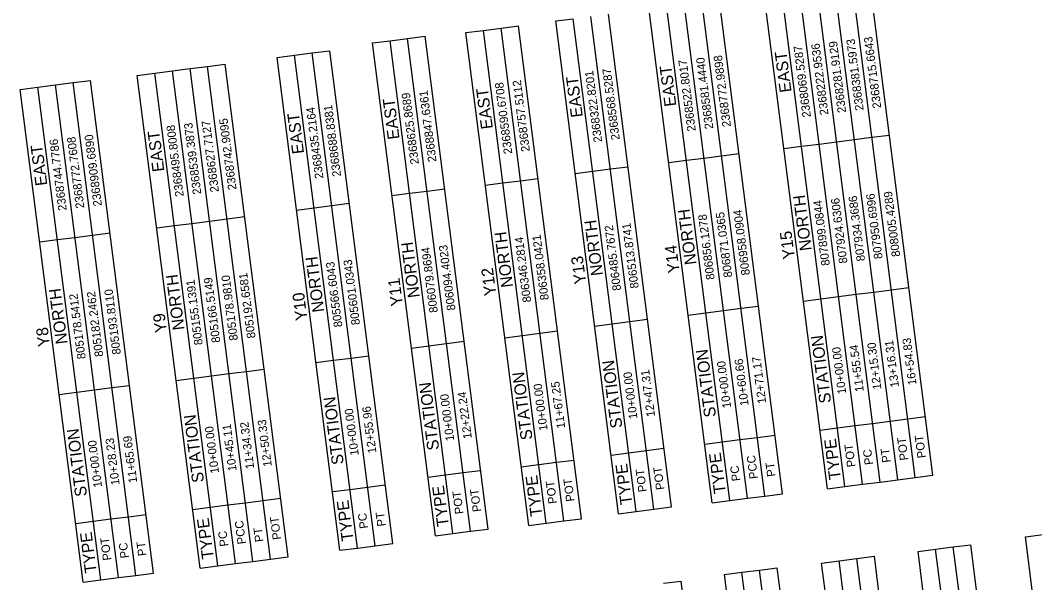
# Model space of a CAD drawing. Extents: x 2364621 to 2374814, y 792603 to 806745.
# Drawn here: x 2366776 to 2370831, y 796538 to 798784 of the extents above; entities that cross this region are included whole.
import ezdxf

# ---------------------------------------------------------------- set-up
doc = ezdxf.new("R2010")
doc.units = 0
for name, color, linetype in [('CTL Sheet Notes CELL', 7, 'Continuous'), ('CTL Sheet Table Cell', 7, 'Continuous'), ('CTL Sheet Text', 7, 'Continuous')]:
    doc.layers.add(name, color=color, linetype=linetype)

msp = doc.modelspace()

# ---------------------------------------------------------------- linework, layer by layer
at = {"layer": 'CTL Sheet Table Cell'}
for p, q in [((2370353.2, 796957.9), (2370101.8, 798926.4)), ((2370423.5, 796966.9), (2370172.1, 798935.4)), ((2370072, 796922), (2369820.6, 798890.5)), ((2370142.3, 796931), (2369890.9, 798899.5)), ((2370212.6, 796939.9), (2369961.2, 798908.5)), ((2370282.9, 796948.9), (2370031.5, 798917.4)), ((2369682, 796874.9), (2369430.6, 798843.4)), ((2369752.3, 796883.9), (2369500.9, 798852.4)), ((2369822.6, 796892.9), (2369571.2, 798861.4)), ((2370001.7, 796913), (2369750.3, 798881.5)), ((2369378.3, 796840.2), (2369126.9, 798808.7)), ((2369541.4, 796857), (2369290, 798825.5)), ((2369611.7, 796865.9), (2369360.3, 798834.4)), ((2368697.3, 798753), (2368767.6, 798761.9)), ((2369019, 796793.4), (2368767.6, 798761.9)), ((2368916, 798781.8), (2368986.3, 798790.8)), ((2369167.4, 796813.3), (2368916, 798781.8)), ((2369237.7, 796822.2), (2368986.3, 798790.8)), ((2369308, 796831.2), (2369056.6, 798799.7)), ((2368324.1, 798711.8), (2368394.4, 798720.8)), ((2368645.8, 796752.3), (2368394.4, 798720.8)), ((2368556.7, 798735), (2368627, 798744)), ((2368808.1, 796766.5), (2368556.7, 798735)), ((2368627, 798744), (2368697.3, 798753)), ((2368878.4, 796775.5), (2368627, 798744)), ((2368948.7, 796784.4), (2368697.3, 798753)), ((2368183.5, 798693.8), (2368253.8, 798702.8)), ((2368434.9, 796725.3), (2368183.5, 798693.8)), ((2368253.8, 798702.8), (2368324.1, 798711.8)), ((2368505.2, 796734.3), (2368253.8, 798702.8)), ((2368575.5, 796743.3), (2368324.1, 798711.8)), ((2367801.9, 798635.9), (2367872.2, 798644.8)), ((2367872.2, 798644.8), (2367942.5, 798653.8)), ((2368123.7, 796676.3), (2367872.2, 798644.8)), ((2367942.5, 798653.8), (2368012.8, 798662.8)), ((2368194, 796685.3), (2367942.5, 798653.8)), ((2368264.3, 796694.3), (2368012.8, 798662.8)), ((2367454.3, 798591.5), (2367524.6, 798600.5)), ((2367524.6, 798600.5), (2367594.9, 798609.4)), ((2367776, 796632), (2367524.6, 798600.5)), ((2367846.3, 796640.9), (2367594.9, 798609.4)), ((2368053.4, 796667.3), (2367801.9, 798635.9)), ((2367243.4, 798564.5), (2367313.7, 798573.5)), ((2367494.8, 796596), (2367243.4, 798564.5)), ((2367313.7, 798573.5), (2367384, 798582.5)), ((2367565.1, 796605), (2367313.7, 798573.5)), ((2367384, 798582.5), (2367454.3, 798591.5)), ((2367635.4, 796614), (2367384, 798582.5)), ((2367705.7, 796623), (2367454.3, 798591.5)), ((2366775.7, 798508.6), (2366846, 798517.6)), ((2366846, 798517.6), (2366916.3, 798526.6)), ((2367097.4, 796549.1), (2366846, 798517.6)), ((2366916.3, 798526.6), (2366986.6, 798535.6)), ((2367167.7, 796558.1), (2366916.3, 798526.6)), ((2366986.6, 798535.6), (2367056.9, 798544.5)), ((2367238, 796567), (2366986.6, 798535.6)), ((2367308.3, 796576), (2367056.9, 798544.5)), ((2367027.1, 796540.1), (2366775.7, 798508.6)), ((2370109.3, 798308.1), (2370179.6, 798317.1)), ((2370179.6, 798317.1), (2370249.9, 798326.1)), ((2369828.1, 798272.2), (2369898.4, 798281.2)), ((2369898.4, 798281.2), (2369968.7, 798290.2)), ((2369968.7, 798290.2), (2370039, 798299.2)), ((2370039, 798299.2), (2370109.3, 798308.1)), ((2369438.1, 798225.1), (2369508.4, 798234.1)), ((2369508.4, 798234.1), (2369578.7, 798243.1)), ((2369578.7, 798243.1), (2369649.1, 798252.1)), ((2369134.4, 798190.4), (2369204.7, 798199.4)), ((2369367.8, 798216.2), (2369438.1, 798225.1)), ((2368775.1, 798143.7), (2368845.4, 798152.6)), ((2368993.8, 798172.5), (2369064.1, 798181.5)), ((2369064.1, 798181.5), (2369134.4, 798190.4)), ((2368401.9, 798102.5), (2368472.2, 798111.5)), ((2368634.5, 798125.7), (2368704.8, 798134.7)), ((2368704.8, 798134.7), (2368775.1, 798143.7)), ((2368261.3, 798084.5), (2368331.6, 798093.5)), ((2368331.6, 798093.5), (2368401.9, 798102.5)), ((2367879.8, 798026.6), (2367950.1, 798035.5)), ((2367950.1, 798035.5), (2368020.4, 798044.5)), ((2368020.4, 798044.5), (2368090.7, 798053.5)), ((2367532.1, 797982.2), (2367602.4, 797991.2)), ((2367602.4, 797991.2), (2367672.7, 798000.1)), ((2367321.2, 797955.2), (2367391.5, 797964.2)), ((2367391.5, 797964.2), (2367461.8, 797973.2)), ((2367461.8, 797973.2), (2367532.1, 797982.2)), ((2366923.8, 797908.3), (2366994.1, 797917.3)), ((2366994.1, 797917.3), (2367064.4, 797926.3)), ((2367064.4, 797926.3), (2367134.7, 797935.2)), ((2366853.5, 797899.3), (2366923.8, 797908.3)), ((2370187.2, 797698.8), (2370257.5, 797707.8)), ((2370257.5, 797707.8), (2370327.8, 797716.8)), ((2369905.9, 797662.9), (2369976.2, 797671.9)), ((2369976.2, 797671.9), (2370046.5, 797680.9)), ((2370046.5, 797680.9), (2370116.9, 797689.8)), ((2370116.9, 797689.8), (2370187.2, 797698.8)), ((2369516, 797615.8), (2369586.3, 797624.8)), ((2369586.3, 797624.8), (2369656.6, 797633.8)), ((2369656.6, 797633.8), (2369726.9, 797642.8)), ((2369212.2, 797581.1), (2369282.5, 797590.1)), ((2369445.7, 797606.9), (2369516, 797615.8)), ((2369071.6, 797563.2), (2369141.9, 797572.2)), ((2369141.9, 797572.2), (2369212.2, 797581.1)), ((2368712.3, 797516.4), (2368782.6, 797525.4)), ((2368782.6, 797525.4), (2368852.9, 797534.4)), ((2368852.9, 797534.4), (2368923.2, 797543.3)), ((2368339.1, 797475.2), (2368409.4, 797484.2)), ((2368409.4, 797484.2), (2368479.7, 797493.2)), ((2368479.7, 797493.2), (2368550, 797502.2)), ((2367957.6, 797417.3), (2368027.9, 797426.2)), ((2368027.9, 797426.2), (2368098.2, 797435.2)), ((2368098.2, 797435.2), (2368168.5, 797444.2)), ((2367610, 797372.9), (2367680.3, 797381.9)), ((2367680.3, 797381.9), (2367750.6, 797390.8)), ((2367399, 797345.9), (2367469.3, 797354.9)), ((2367469.3, 797354.9), (2367539.7, 797363.9)), ((2367539.7, 797363.9), (2367610, 797372.9)), ((2367001.7, 797299), (2367072, 797308)), ((2367072, 797308), (2367142.3, 797317)), ((2367142.3, 797317), (2367212.6, 797325.9)), ((2366931.4, 797290), (2367001.7, 797299)), ((2370182.7, 797174.3), (2370253, 797183.3)), ((2370253, 797183.3), (2370323.3, 797192.2)), ((2370323.3, 797192.2), (2370393.6, 797201.2)), ((2369971.8, 797147.4), (2370042.1, 797156.3)), ((2370042.1, 797156.3), (2370112.4, 797165.3)), ((2370112.4, 797165.3), (2370182.7, 797174.3)), ((2369511.5, 797091.3), (2369581.8, 797100.3)), ((2369581.8, 797100.3), (2369652.1, 797109.3)), ((2369652.1, 797109.3), (2369722.4, 797118.2)), ((2369722.4, 797118.2), (2369792.7, 797127.2)), ((2369207.8, 797056.6), (2369278.1, 797065.6)), ((2369278.1, 797065.6), (2369348.4, 797074.6)), ((2368848.4, 797009.8), (2368918.8, 797018.8)), ((2368918.8, 797018.8), (2368989.1, 797027.8)), ((2369137.5, 797047.6), (2369207.8, 797056.6)), ((2368475.3, 796968.7), (2368545.6, 796977.6)), ((2368545.6, 796977.6), (2368615.9, 796986.6)), ((2368778.1, 797000.8), (2368848.4, 797009.8)), ((2368405, 796959.7), (2368475.3, 796968.7)), ((2370142.3, 796931), (2370212.6, 796939.9)), ((2370212.6, 796939.9), (2370282.9, 796948.9)), ((2370282.9, 796948.9), (2370353.2, 796957.9)), ((2370353.2, 796957.9), (2370423.5, 796966.9)), ((2368023.4, 796901.7), (2368093.7, 796910.7)), ((2368093.7, 796910.7), (2368164, 796919.7)), ((2368164, 796919.7), (2368234.3, 796928.6)), ((2370001.7, 796913), (2370072, 796922)), ((2370072, 796922), (2370142.3, 796931)), ((2367605.5, 796848.3), (2367675.8, 796857.3)), ((2367675.8, 796857.3), (2367746.1, 796866.3)), ((2367746.1, 796866.3), (2367816.4, 796875.3)), ((2369541.4, 796857), (2369611.7, 796865.9)), ((2369611.7, 796865.9), (2369682, 796874.9)), ((2369682, 796874.9), (2369752.3, 796883.9)), ((2369752.3, 796883.9), (2369822.6, 796892.9)), ((2367464.9, 796830.4), (2367535.2, 796839.4)), ((2367535.2, 796839.4), (2367605.5, 796848.3)), ((2369167.4, 796813.3), (2369237.7, 796822.2)), ((2369237.7, 796822.2), (2369308, 796831.2)), ((2369308, 796831.2), (2369378.3, 796840.2)), ((2366997.2, 796774.5), (2367067.5, 796783.4)), ((2367067.5, 796783.4), (2367137.8, 796792.4)), ((2367137.8, 796792.4), (2367208.1, 796801.4)), ((2367208.1, 796801.4), (2367278.4, 796810.4)), ((2368808.1, 796766.5), (2368878.4, 796775.5)), ((2368878.4, 796775.5), (2368948.7, 796784.4)), ((2368948.7, 796784.4), (2369019, 796793.4)), ((2368434.9, 796725.3), (2368505.2, 796734.3)), ((2368505.2, 796734.3), (2368575.5, 796743.3)), ((2368575.5, 796743.3), (2368645.8, 796752.3)), ((2368194, 796685.3), (2368264.3, 796694.3)), ((2370793.6, 796721.1), (2370863.9, 796730.1)), ((2371045.1, 794752.6), (2370793.6, 796721.1)), ((2368053.4, 796667.3), (2368123.7, 796676.3)), ((2368123.7, 796676.3), (2368194, 796685.3)), ((2370364.3, 796662.7), (2370434.6, 796671.7)), ((2370615.7, 794694.2), (2370364.3, 796662.7)), ((2370434.6, 796671.7), (2370504.9, 796680.6)), ((2370686, 794703.2), (2370434.6, 796671.7)), ((2370504.9, 796680.6), (2370575.2, 796689.6)), ((2370756.3, 794712.1), (2370504.9, 796680.6)), ((2370826.6, 794721.1), (2370575.2, 796689.6)), ((2367565.1, 796605), (2367635.4, 796614)), ((2367635.4, 796614), (2367705.7, 796623)), ((2367705.7, 796623), (2367776, 796632)), ((2367776, 796632), (2367846.3, 796640.9)), ((2369978.6, 796616.3), (2370048.9, 796625.3)), ((2370230, 794647.8), (2369978.6, 796616.3)), ((2370048.9, 796625.3), (2370119.2, 796634.3)), ((2370300.3, 794656.8), (2370048.9, 796625.3)), ((2370119.2, 796634.3), (2370189.5, 796643.2)), ((2370370.6, 794665.7), (2370119.2, 796634.3)), ((2370440.9, 794674.7), (2370189.5, 796643.2)), ((2367238, 796567), (2367308.3, 796576)), ((2367494.8, 796596), (2367565.1, 796605)), ((2369590.2, 796570.5), (2369660.5, 796579.5)), ((2369841.6, 794602), (2369590.2, 796570.5)), ((2369660.5, 796579.5), (2369730.8, 796588.4)), ((2369911.9, 794610.9), (2369660.5, 796579.5)), ((2369730.8, 796588.4), (2369801.1, 796597.4)), ((2369982.2, 794619.9), (2369730.8, 796588.4)), ((2370052.5, 794628.9), (2369801.1, 796597.4)), ((2367027.1, 796540.1), (2367097.4, 796549.1)), ((2367097.4, 796549.1), (2367167.7, 796558.1)), ((2367167.7, 796558.1), (2367238, 796567)), ((2369346.9, 796535.5), (2369417.3, 796544.5)), ((2369668.7, 794575.9), (2369417.3, 796544.5))]:
    msp.add_line(p, q, dxfattribs=at)

# ---------------------------------------------------------------- texts
at = {"layer": 'CTL Sheet Notes CELL'}
for s, p in [('EAST', (2369858.7, 798499.1)), ('EAST', (2369398.4, 798443)), ('EAST', (2369024.4, 798399.4)), ('EAST', (2368665, 798352.6)), ('EAST', (2368291.9, 798311.4)), ('EAST', (2367910.3, 798253.4)), ('EAST', (2367351.8, 798182.1)), ('EAST', (2366884.1, 798126.2)), ('NORTH', (2369939.5, 797866.5)), ('NORTH', (2369479.2, 797810.5)), ('NORTH', (2369105.2, 797766.8)), ('NORTH', (2368745.8, 797720)), ('Y15', (2369872.2, 797833.8)), ('NORTH', (2368372.6, 797678.9)), ('Y14', (2369411.9, 797777.7)), ('NORTH', (2367991.1, 797620.9)), ('Y13', (2369037.9, 797734)), ('Y12', (2368678.6, 797687.2)), ('NORTH', (2367432.6, 797549.6)), ('Y11', (2368305.4, 797646.1)), ('NORTH', (2366964.9, 797493.6)), ('Y10', (2367923.8, 797588.1)), ('Y9', (2367362.3, 797540)), ('Y8', (2366894.7, 797484.1)), ('STATION', (2370017.2, 797257.6)), ('STATION', (2369557, 797201.6)), ('STATION', (2369182.9, 797157.9)), ('STATION', (2368823.6, 797111.1)), ('STATION', (2368450.4, 797069.9)), ('STATION', (2368068.9, 797012)), ('STATION', (2367510.4, 796940.6)), ('STATION', (2367042.7, 796884.7)), ('TYPE', (2370056.2, 796952.4)), ('TYPE', (2369595.9, 796896.4)), ('TYPE', (2369221.9, 796852.7)), ('TYPE', (2368862.6, 796805.9)), ('TYPE', (2368489.4, 796764.7)), ('TYPE', (2368107.9, 796706.8)), ('TYPE', (2367549.3, 796635.4)), ('TYPE', (2367081.6, 796579.5))]:
    msp.add_text(s, height=47.25, rotation=97.2784, dxfattribs=at).set_placement(p)
at = {"layer": 'CTL Sheet Text'}
for s, p in [('2368069.5287', (2369936.2, 798398.7)), ('2368222.9536', (2370006.5, 798407.7)), ('2368281.9129', (2370076.8, 798416.7)), ('2368381.5973', (2370147.1, 798425.7)), ('2368715.6643', (2370217.4, 798434.6)), ('2368772.9898', (2369616.5, 798360.6)), ('2368522.8017', (2369475.9, 798342.7)), ('2368581.4440', (2369546.2, 798351.7)), ('2368322.8201', (2369101.8, 798299)), ('2368568.5287', (2369172.1, 798308)), ('2368590.6708', (2368742.5, 798252.2)), ('2368757.5112', (2368812.8, 798261.2)), ('2368625.8689', (2368369.3, 798211)), ('2368847.6361', (2368439.6, 798220)), ('2368435.2164', (2367987.8, 798153.1)), ('2368688.8381', (2368058.1, 798162)), ('2368495.8008', (2367429.3, 798081.8)), ('2368539.3873', (2367499.6, 798090.7)), ('2368627.7127', (2367569.9, 798099.7)), ('2368742.9095', (2367640.2, 798108.7)), ('2368772.7608', (2367031.9, 798034.8)), ('2368909.6890', (2367102.2, 798043.8)), ('2368744.7786', (2366961.6, 798025.8)), ('807924.6306', (2370082.2, 797815)), ('807934.3686', (2370152.5, 797824)), ('807950.6996', (2370222.8, 797833)), ('808005.4289', (2370293.1, 797841.9)), ('807899.0844', (2370011.8, 797806)), ('806856.1278', (2369551.6, 797750)), ('806871.0365', (2369621.9, 797759)), ('806958.0904', (2369692.2, 797767.9)), ('806485.7672', (2369177.5, 797706.3)), ('806513.8741', (2369247.8, 797715.3)), ('806346.2814', (2368818.2, 797659.5)), ('806358.0421', (2368888.5, 797668.5)), ('806079.8694', (2368445, 797618.4)), ('806094.4023', (2368515.3, 797627.3)), ('805601.0343', (2368133.8, 797569.3)), ('805566.6043', (2368063.5, 797560.4)), ('805155.1391', (2367505, 797489.1)), ('805166.5149', (2367575.3, 797498)), ('805178.9810', (2367645.6, 797507)), ('805192.6581', (2367715.9, 797516)), ('805193.8110', (2367177.9, 797451.1)), ('805178.5412', (2367037.3, 797433.1)), ('805182.2462', (2367107.6, 797442.1)), ('13+16.31', (2370288.2, 797320.4)), ('16+54.83', (2370358.5, 797329.3)), ('10+00.00', (2370077.3, 797293.4)), ('11+55.54', (2370147.6, 797302.4)), ('12+15.30', (2370217.9, 797311.4)), ('10+00.00', (2369617, 797237.4)), ('10+60.66', (2369687.3, 797246.3)), ('12+71.17', (2369757.6, 797255.3)), ('12+47.31', (2369313.3, 797202.7)), ('11+67.25', (2368954, 797155.9)), ('10+00.00', (2369243, 797193.7)), ('12+22.24', (2368580.8, 797114.7)), ('10+00.00', (2368883.7, 797146.9)), ('10+00.00', (2368510.5, 797105.7)), ('10+00.00', (2368129, 797047.8)), ('12+55.96', (2368199.3, 797056.7)), ('11+34.32', (2367711, 796994.4)), ('12+50.33', (2367781.3, 797003.4)), ('10+00.00', (2367570.4, 796976.5)), ('10+45.11', (2367640.7, 796985.4)), ('10+00.00', (2367102.7, 796920.5)), ('10+28.23', (2367173, 796929.5)), ('11+65.69', (2367243.3, 796938.5)), ('POT', (2370325.5, 797028.4)), ('POT', (2370395.8, 797037.4)), ('POT', (2370114.6, 797001.5)), ('PC ', (2370184.9, 797010.5)), ('PT ', (2370255.2, 797019.5)), ('PCC', (2369724.6, 796954.4)), ('POT', (2369280.3, 796901.8)), ('POT', (2369350.6, 796910.7)), ('PC ', (2369654.3, 796945.5)), ('PT ', (2369794.9, 796963.4)), ('POT', (2368921, 796855)), ('POT', (2368991.3, 796864)), ('POT', (2368547.8, 796813.8)), ('POT', (2368618.1, 796822.8)), ('PC ', (2368166.2, 796755.8)), ('PT ', (2368236.5, 796764.8)), ('PCC', (2367678, 796693.5)), ('POT', (2367818.6, 796711.5)), ('PC ', (2367607.7, 796684.5)), ('PT ', (2367748.3, 796702.5)), ('POT', (2367140, 796628.6)), ('PC ', (2367210.3, 796637.6)), ('PT ', (2367280.6, 796646.6))]:
    msp.add_text(s, height=33.75, rotation=97.2784, dxfattribs=at).set_placement(p)

doc.saveas('drawing.dxf')
